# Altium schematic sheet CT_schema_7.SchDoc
size 278 x 170 mm
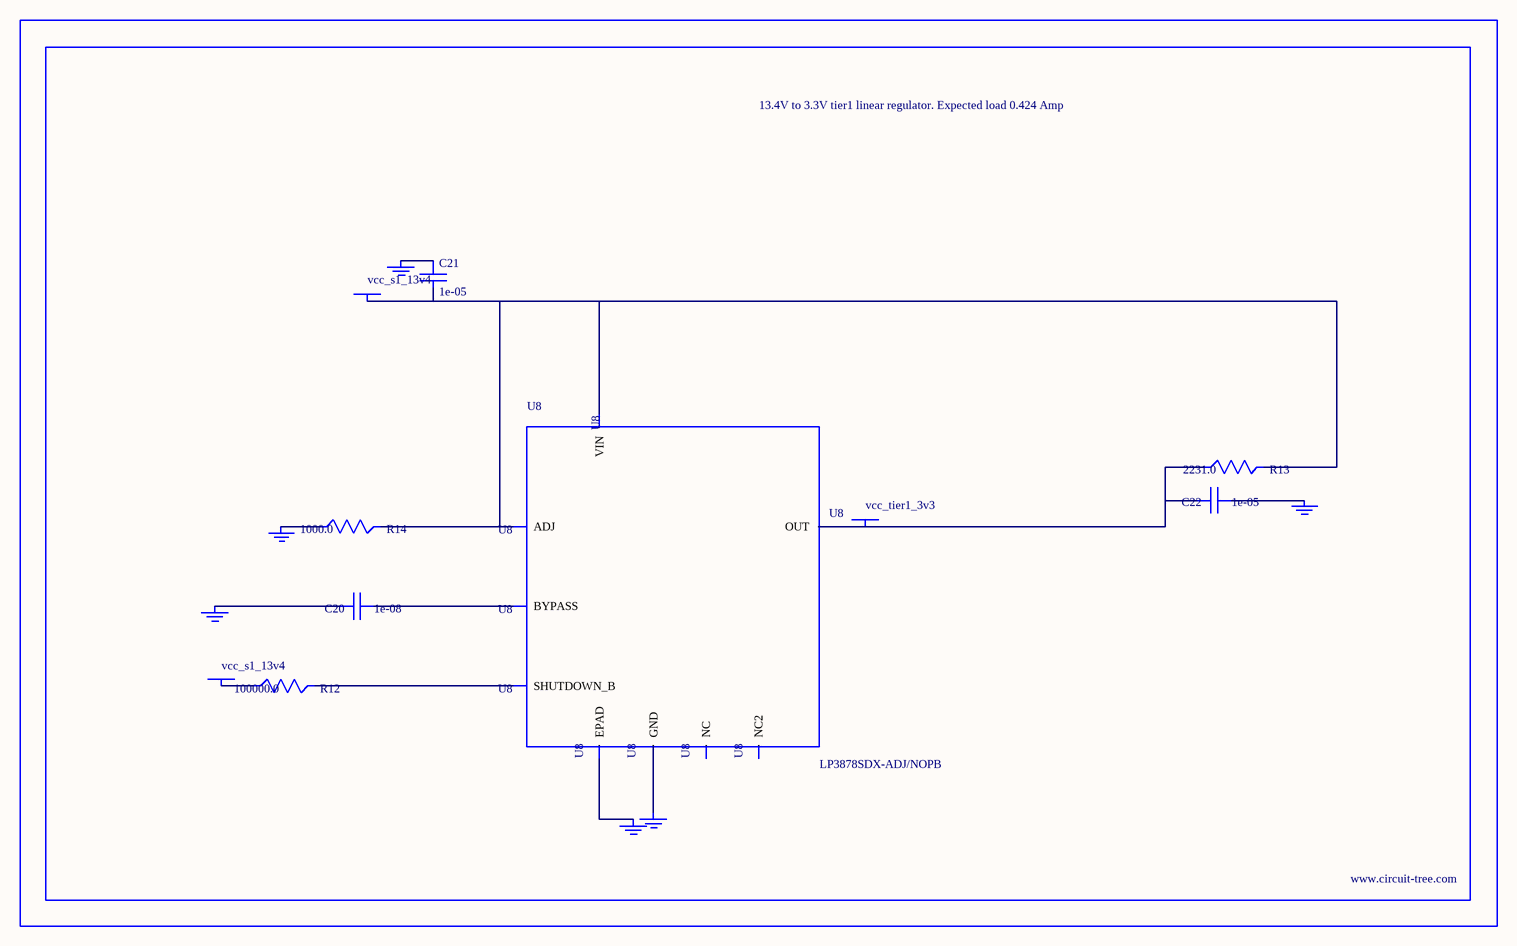
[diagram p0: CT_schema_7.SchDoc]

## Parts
BORDER6  (no value)
C20  1e-08  [C0402]
C21  1e-05  [C1210]
C22  1e-05  [C1210]
GND_INSTANCE_6_0  (no value)
GND_INSTANCE_6_1  (no value)
GND_INSTANCE_6_2  (no value)
GND_INSTANCE_6_3  (no value)
GND_INSTANCE_6_4  (no value)
GND_INSTANCE_6_5  (no value)
POWER_INSTANCE_6_0  vcc_s1_13v4
POWER_INSTANCE_6_1  vcc_s1_13v4
POWER_INSTANCE_6_2  vcc_tier1_3v3
R12  100000.0  [R0603]
R13  2231.0  [R0603]
R14  1000.0  [R0603]
U8  LP3878SDX-ADJ/NOPB  [WSON-8]

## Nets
NetC20_1: C20.1 U8.1(BYPASS)
NetC20_2: C20.2 GND_INSTANCE_6_0.0(GND)
NetC21_1: C21.1 GND_INSTANCE_6_1.0(GND)
NetC21_2: C21.2 POWER_INSTANCE_6_0.0(PWR) R13.2 R14.2 U8.4(VIN) U8.6(ADJ)
NetC22_1: C22.1 GND_INSTANCE_6_2.0(GND)
NetC22_2: C22.2 POWER_INSTANCE_6_2.0(PWR) R13.1 U8.5(OUT)
NetGND_INSTANCE_6_3_0: GND_INSTANCE_6_3.0(GND) R14.1
NetGND_INSTANCE_6_4_0: GND_INSTANCE_6_4.0(GND) U8.PAD(EPAD)
NetGND_INSTANCE_6_5_0: GND_INSTANCE_6_5.0(GND) U8.3(GND)
NetPOWER_INSTANCE_6_1_0: POWER_INSTANCE_6_1.0(PWR) R12.1
NetR12_2: R12.2 U8.8(SHUTDOWN_B)

Not connected (* = marked no-connect by the designer): U8 2(NC) 7(NC2)

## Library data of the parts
BORDER6 = BORDER_PAGE6
C20 = C0402C103K3RAC
C21 = C1210C106K5PACTU
C22 = GRM32DR61E106MA12L
GND_INSTANCE_6_0-GND_INSTANCE_6_5 = GND
POWER_INSTANCE_6_0-POWER_INSTANCE_6_2 = PWR
R12 = RC0603JR-07100KL
R13 = R13
R14 = RC0603JR-071KL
